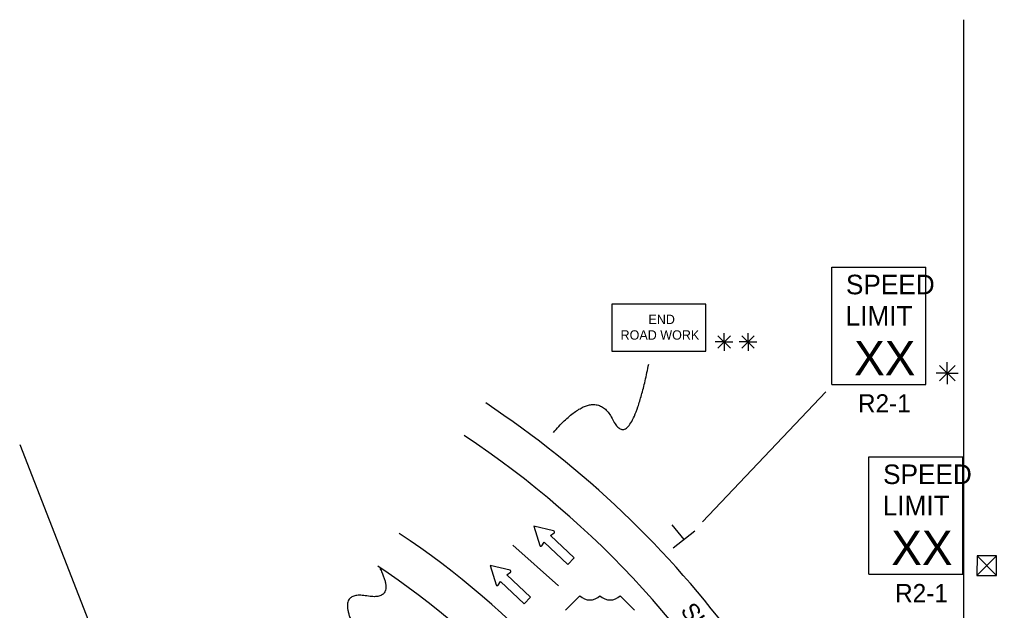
# Model space of a CAD drawing. Extents: x 16512 to 19509, y 5761 to 6974.
# Drawn here: x 16595 to 16998.2, y 6732.7 to 6974.1 of the extents above; entities that cross this region are included whole.
import ezdxf

# ---------------------------------------------------------------- set-up
doc = ezdxf.new("R2010")
doc.units = 0
for name, color, linetype in [('ALI_LEGAL_EX', 7, 'Continuous'), ('MT_SCRATCH_LEVEL_E', 7, 'Continuous'), ('PAVT_EDGE_EX', 7, 'Continuous'), ('TRAFFIC_SIGNS_PR', 7, 'Continuous'), ('TYPICAL_EX', 7, 'Continuous'), ('TYPICAL_TEXT_DIMEN_PR', 7, 'Continuous')]:
    doc.layers.add(name, color=color, linetype=linetype)

msp = doc.modelspace()

# ---------------------------------------------------------------- linework, layer by layer
at = {"layer": 'ALI_LEGAL_EX'}
for p, q in [((16980.68, 6974.12), (16980.68, 6155.98)), ((16980.68, 6922.21), (16980.68, 6058.3)), ((16594.98, 6800.51), (16817, 6232.14))]:
    msp.add_line(p, q, dxfattribs=at)
msp.add_lwpolyline([(16815.12, 6742.72), (16796.45, 6759.35)], dxfattribs=at)
at = {"layer": 'MT_SCRATCH_LEVEL_E'}
for p, q in [((16813.17, 6765.15), (16805.06, 6767.11)), ((16805.06, 6767.11), (16807.49, 6759.15)), ((16811.89, 6763.25), (16813.34, 6764.33)), ((16821.51, 6754.14), (16811.89, 6763.25)), ((16808.32, 6759.03), (16809.31, 6760.54)), ((16809.31, 6760.54), (16818.94, 6751.42)), ((16818.94, 6751.42), (16821.51, 6754.14)), ((16795.35, 6749.07), (16787.24, 6751.04)), ((16787.24, 6751.04), (16789.67, 6743.07)), ((16794.07, 6747.18), (16795.52, 6748.25)), ((16803.69, 6738.06), (16794.07, 6747.18)), ((16790.5, 6742.95), (16791.5, 6744.46)), ((16791.5, 6744.46), (16801.12, 6735.34)), ((16801.12, 6735.34), (16803.69, 6738.06))]:
    msp.add_line(p, q, dxfattribs=at)
for centre, start, end in [((16813.05, 6764.7), 306.594, 76.331), ((16807.94, 6759.29), 196.9827, 326.5217), ((16795.23, 6748.62), 306.594, 76.331), ((16790.12, 6743.21), 196.9827, 326.5217)]:
    msp.add_arc(centre, 0.463, start, end, dxfattribs=at)
at = {"layer": 'PAVT_EDGE_EX'}
for centre, radius, start, end in [((16562.45, 6480.53), 404, 15.917, 56.5037), ((16562.45, 6480.53), 388, 0, 56.5037), ((17314.45, 6480.53), 380, 121.9327, 163.0483), ((17314.45, 6480.53), 364, 121.9327, 180), ((16562.45, 6480.53), 340, 0, 56.5037), ((16562.45, 6480.53), 324, 0, 56.5037)]:
    msp.add_arc(centre, radius, start, end, dxfattribs=at)
at = {"layer": 'TRAFFIC_SIGNS_PR'}
for p, q in [((16926.87, 6873), (16965.27, 6873)), ((16926.87, 6825), (16926.87, 6873)), ((16965.27, 6825), (16965.27, 6873)), ((16926.87, 6825), (16965.27, 6825)), ((16942.04, 6795.43), (16980.44, 6795.43)), ((16942.04, 6747.43), (16942.04, 6795.43)), ((16980.44, 6747.43), (16980.44, 6795.43)), ((16942.04, 6747.43), (16980.44, 6747.43))]:
    msp.add_line(p, q, dxfattribs=at)
msp.add_lwpolyline([(16836.92, 6838.58), (16875.32, 6838.58), (16875.32, 6857.78), (16836.92, 6857.78)], close=True, dxfattribs=at)
at = {"layer": 'TYPICAL_EX'}
for p, q in [((16817.96, 6732.69), (16823.85, 6738.58)), ((16846.26, 6732.69), (16840.36, 6738.58))]:
    msp.add_line(p, q, dxfattribs=at)
for centre in [(16827.98, 6742.88), (16836.23, 6742.88)]:
    msp.add_arc(centre, 5.96, 226.1404, 313.8596, dxfattribs=at)
at = {"layer": 'TYPICAL_TEXT_DIMEN_PR'}
for p, q in [((16882.87, 6842.4), (16882.87, 6845.97)), ((16892.61, 6842.4), (16892.61, 6845.97)), ((16882.87, 6842.4), (16879.24, 6842.4)), ((16880.32, 6844.95), (16885.42, 6839.85)), ((16885.42, 6844.95), (16880.32, 6839.85)), ((16882.87, 6842.4), (16885.42, 6842.4)), ((16882.87, 6842.4), (16886.45, 6842.4)), ((16882.87, 6842.4), (16882.87, 6838.8)), ((16892.61, 6842.4), (16888.99, 6842.4)), ((16890.06, 6844.95), (16895.16, 6839.85)), ((16895.16, 6844.95), (16890.06, 6839.85)), ((16892.61, 6842.4), (16895.16, 6842.4)), ((16892.61, 6842.4), (16896.2, 6842.4)), ((16892.61, 6842.4), (16892.61, 6838.8)), ((16974.05, 6829.62), (16974.05, 6834.07)), ((16970.87, 6832.8), (16977.24, 6826.43)), ((16977.24, 6832.8), (16970.87, 6826.43)), ((16974.05, 6829.62), (16969.52, 6829.62)), ((16974.05, 6829.62), (16977.24, 6829.62)), ((16974.05, 6829.62), (16978.53, 6829.62)), ((16974.05, 6829.62), (16974.05, 6825.12)), ((16924.47, 6822.03), (16873.98, 6768.85)), ((16866.48, 6761.57), (16861.61, 6767.65)), ((16870.87, 6765.09), (16862.09, 6758.06)), ((16986.19, 6746.9), (16994.19, 6754.9)), ((16986.2, 6754.9), (16994.19, 6746.9))]:
    msp.add_line(p, q, dxfattribs=at)
msp.add_lwpolyline([(16986.2, 6754.9), (16986.19, 6746.9), (16994.19, 6746.9), (16994.19, 6754.9)], close=True, dxfattribs=at)
for points in [[(16813.09, 6805.35), (16830.11, 6825.17), (16844.49, 6796.18), (16852.06, 6833.31)], [(16742.2, 6749.78), (16748.98, 6736.43), (16724.69, 6740.64), (16731.07, 6727.07)]]:
    msp.add_open_spline(points, degree=2, dxfattribs=at)

# ---------------------------------------------------------------- texts
at = {"layer": 'TRAFFIC_SIGNS_PR'}
for s, height, p in [('SPEED', 8, (16932.63, 6861.86)), ('LIMIT', 8, (16932.47, 6849.06)), ('END', 3.831, (16851.92, 6849.71)), ('ROAD WORK', 3.831, (16840.53, 6843.32)), ('XX', 14.031, (16935.98, 6828.76)), ('R2-1', 7.44, (16937.54, 6813.56)), ('SPEED', 8, (16947.81, 6784.29)), ('LIMIT', 8, (16947.65, 6771.49)), ('XX', 14.031, (16951.16, 6751.19)), ('R2-1', 7.44, (16952.72, 6735.99))]:
    msp.add_text(s, height=height, dxfattribs=at).set_placement(p)
at = {"layer": 'TYPICAL_TEXT_DIMEN_PR'}
msp.add_text('SHOULDER', height=7, rotation=305.9489, dxfattribs=at).set_placement((16864.74, 6732.56))

doc.saveas('drawing.dxf')
